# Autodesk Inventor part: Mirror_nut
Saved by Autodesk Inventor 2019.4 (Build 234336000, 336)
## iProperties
Created: 2019-10
Part Number: Mirror_nut
Material: Generic
Document SubType Name: Modeling
Designer: Administrator
Density: 1 g/cm^3
Appearance: Default
Title: Mirror_nut
Author: Administrator
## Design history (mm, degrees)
feature "Body1"
body "Solid1"
